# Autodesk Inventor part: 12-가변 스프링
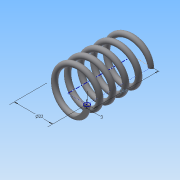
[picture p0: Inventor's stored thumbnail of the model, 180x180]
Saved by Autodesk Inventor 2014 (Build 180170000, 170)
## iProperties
Created: 2015-09
Part Number: 12-가변 스프링
Material: 강철, 탄소
Document SubType Name: Modeling
Designer: study
Density: 1 g/cm^3
Appearance: 반연마
Mass: 2.3997 g
Surface Area: 32.5491 cm^2
Volume: 2.3997 cm^3
Author: study
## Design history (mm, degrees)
sketch "스케치1"
  geometry: L1 (0, 0)-(11, 0); L2 (11, 0)-(11, 36.411); L3 (11, 36.411)-(0, 36.411); L4 (0, 36.411)-(0, 0); C1 r 1.5 at (11, 0)
  constraints: 8 end point, 2 parallel, 1 centre point, 1 coincident, 1 horizontal, 1 perpendicular
  dimensions: "d0" = 22 diameter of L2 L4; "d1" = 36.4112 distance of L1.end L2.end (derived); "d2" = 3 diameter of C1
feature "코일1" sketch "스케치1" pitch "d3" = 10; turns "d5" = 5; dims "d4" = 36.4112 (= d1), "d6" = 0, angle "d7" = 90 deg, angle "d8" = 90 deg, "d9" = 0, "d10" = 0
node "작업 평면1"
sketch "스케치2"
  geometry: L1 (-12.5, 0)-(-9.5, 0) reference; 1 further point
  constraints: 1 horizontal alignment
extrude "돌출1" cut sketch "스케치2" stored distance "d12" = 10; taper "d13" = 0 deg
node "작업 평면2"
sketch "스케치3"
  geometry: L1 (-9.5, 0)-(-12.5, 0) reference; 1 further point
  constraints: 1 horizontal alignment
extrude "돌출2" cut sketch "스케치3" stored distance "d15" = 10; taper "d16" = 0 deg
node "솔리드1"
node "절단 모서리 투영1"
node "절단 모서리 투영2"
other parameters: "d11" = 0, "d14" = 36.4112 (= d1)
